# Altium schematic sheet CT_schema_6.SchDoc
size 400 x 245 mm
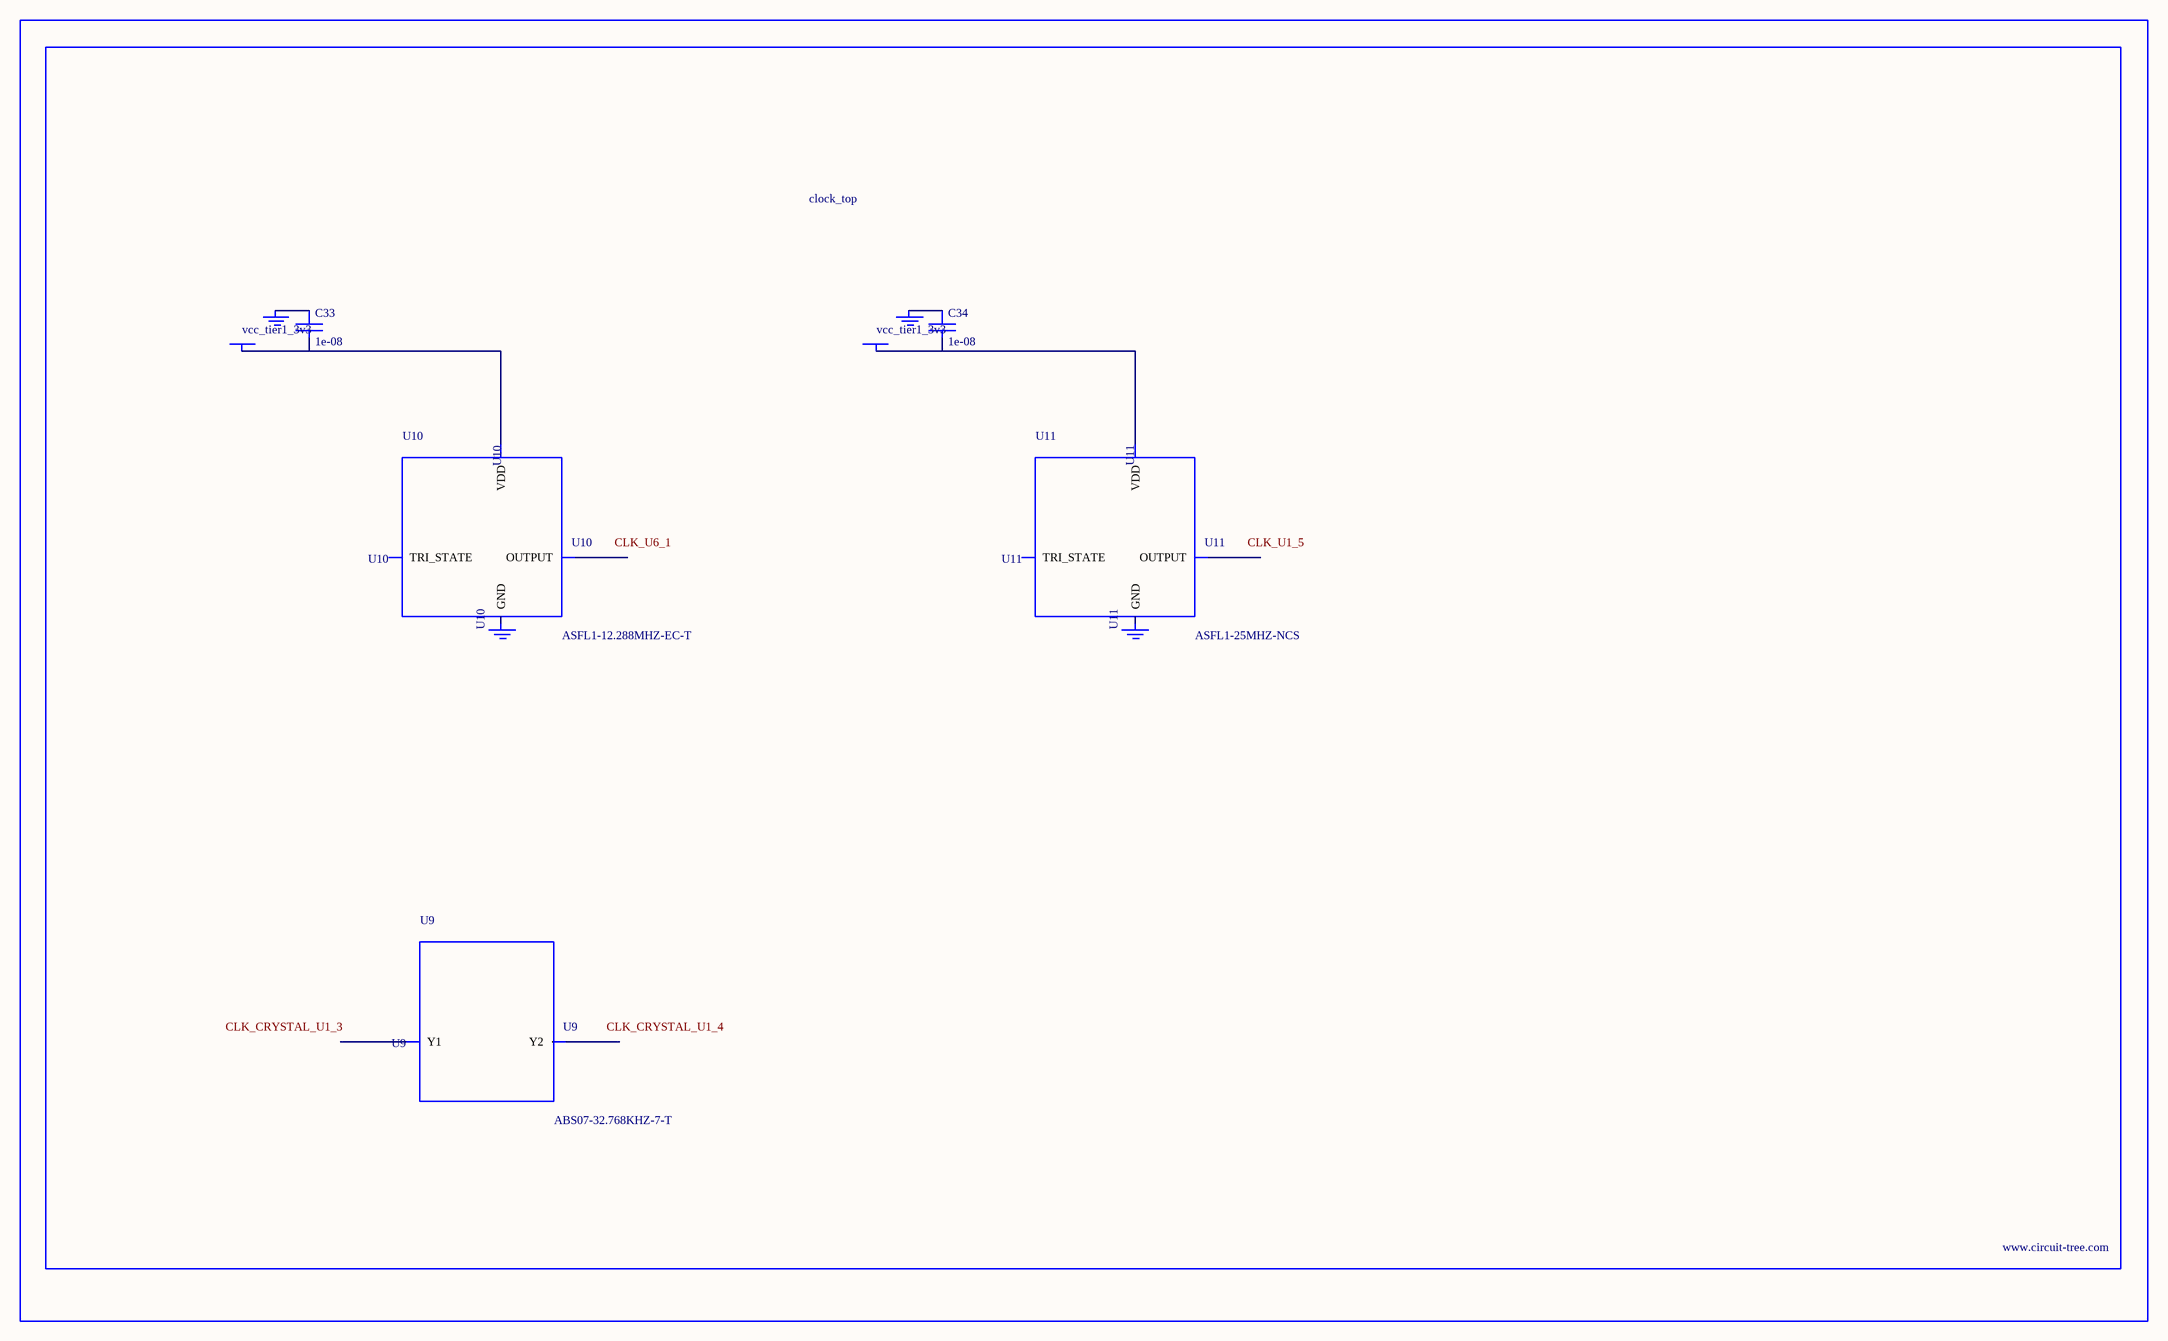
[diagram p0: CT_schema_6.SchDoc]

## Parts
BORDER5  (no value)
C33  1e-08  [C0402]
C34  1e-08  [C0402]
GND_INSTANCE_5_0  (no value)
GND_INSTANCE_5_1  (no value)
GND_INSTANCE_5_2  (no value)
GND_INSTANCE_5_3  (no value)
POWER_INSTANCE_5_0  vcc_tier1_3v3
POWER_INSTANCE_5_1  vcc_tier1_3v3
U9  ABS07-32.768KHZ-7-T  [ABS07-32.768KHZ-7-T]
U10  ASFL1-12.288MHZ-EC-T  [ASFL1]
U11  ASFL1-25MHZ-NCS  [ASFL1]

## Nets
NetC33_1: C33.1 GND_INSTANCE_5_0.0(GND)
NetC33_2: C33.2 POWER_INSTANCE_5_0.0(PWR) U10.4(VDD)
NetC34_1: C34.1 GND_INSTANCE_5_2.0(GND)
NetC34_2: C34.2 POWER_INSTANCE_5_1.0(PWR) U11.4(VDD)

Not connected (* = marked no-connect by the designer): GND_INSTANCE_5_1 0(GND); GND_INSTANCE_5_3 0(GND); U9 1(Y1) 2(Y2); U10 1(TRI_STATE) 2(GND) 3(OUTPUT); U11 1(TRI_STATE) 2(GND) 3(OUTPUT)

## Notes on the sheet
- Labels drawn without touching a wire or pin: CLK_CRYSTAL_U1_3, CLK_CRYSTAL_U1_4, CLK_U1_5, CLK_U6_1

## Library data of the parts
BORDER5 = BORDER_PAGE5
C33 C34 = C0402C103K3RAC
GND_INSTANCE_5_0-GND_INSTANCE_5_3 = GND
POWER_INSTANCE_5_0 POWER_INSTANCE_5_1 = PWR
